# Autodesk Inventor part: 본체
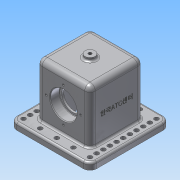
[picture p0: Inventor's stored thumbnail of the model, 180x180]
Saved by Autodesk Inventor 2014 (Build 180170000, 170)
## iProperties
Created: 2018-11
Part Number: 본체
Material: 알루미늄 6061
Document SubType Name: Modeling
Designer: Administrator
Density: 2.71 g/cm^3
Appearance: 알루미늄 - 평지
Mass: 1020.37 g
Surface Area: 790.556 cm^2
Volume: 376.52 cm^3
Author: Administrator
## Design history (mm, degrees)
sketch "스케치1"
  geometry: L1 (-60, -60)-(60, -60); L2 (60, -60)-(60, 60); L3 (60, 60)-(-60, 60); L4 (-60, 60)-(-60, -60); L5 (-60, -60)-(60, 60); L6 (60, -60)-(-60, 60); 1 further point
  constraints: 12 end point, 2 midpoint, 2 parallel, 1 horizontal, 1 perpendicular
  dimensions: "d0" = 120 distance of L3.end L2.end; "d1" = 120 distance of L2.end L1.end
extrude "돌출1" new body sketch "스케치1" distance "d2" = 10; taper "d3" = 0 deg
sketch "스케치2"
  geometry: L1 (-40, -40)-(40, -40); L2 (40, -40)-(40, 40); L3 (40, 40)-(-40, 40); L4 (-40, 40)-(-40, -40); L5 (-40, -40)-(40, 40); L6 (40, -40)-(-40, 40); 1 further point
  constraints: 12 end point, 2 midpoint, 2 parallel, 1 horizontal, 1 perpendicular
  dimensions: "d4" = 80 distance of L3.end L2.end; "d5" = 80 distance of L2.end L1.end
extrude "돌출2" join sketch "스케치2" distance "d6" = 80; taper "d7" = 0 deg
sketch "스케치4"
  geometry: C1 r 7.5 at (0, 0); 1 further point
  constraints: 1 centre point, 1 coincident
  dimensions: "d10" = 15 diameter of C1
extrude "돌출3" join sketch "스케치4" distance "d11" = 5; taper "d12" = 0 deg
node "작업 평면3"
sketch "스케치7"
  geometry: L1 (-60, 0)-(-60, 10) reference; L2 (-60, 10)-(-40, 10) reference; L3 (-40, 10)-(-40, 90) reference; L4 (-40, 90)-(-7.5, 90) reference; L5 (-7.5, 90)-(-7.5, 95) reference; L6 (-7.5, 95)-(7.5, 95) reference; L7 (7.5, 95)-(7.5, 90) reference; L8 (7.5, 90)-(40, 90) reference; L9 (40, 90)-(40, 10) reference; L10 (40, 10)-(60, 10) reference; L11 (60, 10)-(60, 0) reference; L12 (60, 0)-(-60, 0) reference; L13 (0, 0)-(0, 48); L14 (0, 48)-(-40, 48); L15 (-40, 48)-(-40, 68); L16 (-40, 68)-(-26, 68); L17 (-26, 68)-(-26, 64.5); L18 (-26, 64.5)-(-23, 64.5); L19 (-23, 64.5)-(-23, 48); L20 (23, 64.5)-(23, 48); L21 (26, 64.5)-(23, 64.5); L22 (26, 68)-(26, 64.5); L23 (40, 68)-(26, 68); L24 (40, 48)-(40, 68); L25 (0, 48)-(40, 48)
  constraints: 26 end point, 6 symmetric about line, 5 perpendicular, 4 point on line, 1 parallel
  dimensions: "d28" = 48 distance of L13.start L13.end; "d29" = 14 distance of L15.end L16.end; "d30" = 3 distance of L17.end L18.end; "d31" = 40 diameter of L16 L14; "d32" = 33 diameter of L18 L14
revolve "회전1" sketch "스케치7" stored, may be unused: angle "d33" = 90 deg
sketch "스케치8"
  geometry: L1 (30, -23)-(-30, -23); L2 (-30, -23)-(-30, 23); L3 (-30, 23)-(30, 23); L4 (30, 23)-(30, -23); L5 (30, -23)-(-30, 23); L6 (-30, -23)-(30, 23); 1 further point
  constraints: 12 end point, 2 midpoint, 2 parallel, 1 horizontal, 1 perpendicular
  dimensions: "d34" = 60 distance of L2.end L3.end; "d35" = 46 distance of L1.end L2.end
extrude "돌출4" cut sketch "스케치8" distance "d36" = 80; taper "d37" = 0 deg
sketch "스케치9" dims "d38" = 52
  geometry: L1 (100, 0)-(100, -10) reference; L2 (100, -10)-(-20, -10) reference; L3 (-20, -10)-(-20, 0) reference; L4 (-20, 0)-(0, 0) reference; L5 (0, 0)-(80, 0) reference; L6 (80, 0)-(100, 0) reference; L7 (0, 0)-(0, 80) reference; L8 (0, 80)-(80, 80) reference; L9 (80, 80)-(80, 0) reference; C1 r 20 at (40, 38) reference; C2 r 20 at (40, 38) reference; 3 further points
  constraints: 2 horizontal alignment, 1 coincident, 2 other
hole "구멍1" sketch "스케치9" at (66, 38) diameter "d39" = 3.242; stored, may be unused: countersink angle "d43" = 90 deg, drill point angle "d45" = 118 deg; dims "d40" = 8, "d41" = 4, "d42" = 2, "d44" = 10
hole "구멍2" diameter "d51" = 4.917; stored, may be unused: countersink angle "d55" = 90 deg, drill point angle "d57" = 0 deg; dims "d49" = 10, "d50" = 10, "d52" = 8, "d53" = 4, "d54" = 2, "d56" = 10
fillet "모깎기1" dims "d58" = 3
chamfer "모따기1" distance "d59" = 1; stored, may be unused: second distance "d60" = 2, angle "d61" = 45 deg
fillet "모깎기2" dims "d62" = 10
sketch "스케치10"
  geometry: A1 r 10 centre (-50, 50) between (-50, 60) and (-60, 50) reference; 2 further points
  constraints: 1 coincident
hole "구멍3" sketch "스케치10" at (-50, 50) diameter "d63" = 6.6; stored, may be unused: countersink angle "d67" = 90 deg, drill point angle "d69" = 0 deg; dims "d64" = 8, "d65" = 4, "d66" = 2, "d68" = 10
fillet "모깎기3" dims "d76" = 8
fillet "모깎기4" dims "d77" = 8
sketch "스케치13"
  geometry: L1 (10, -18)-(10, 82) reference; L2 (-85, 39.5)-(-85, 24.5) reference; 3 further points
  constraints: 1 horizontal alignment, 1 midpoint, 1 other
  dimensions: "d80" = 48 distance from line of L1 point (-38, 32)
feature "엠보싱1" sketch "스케치13" dims "d0" = 120, "d1" = 120, "d81" = 0.5, "d82" = 0
fillet "모깎기5" dims "d83" = 3
fillet "모깎기6" dims "d84" = 3
fillet "모깎기7" dims "d85" = 3
fillet "모깎기8" dims "d86" = 0.6
fillet "모깎기9" dims "d93" = 3
chamfer "모따기2" distance "d94" = 1; stored, may be unused: second distance "d95" = 2, angle "d96" = 45 deg
node "솔리드1"
pattern_circular "원형 패턴1" dims angle "d47" = 360 deg
mirror "대칭1"
mirror "대칭2"
mirror "대칭3"
pattern_linear "직사각형 패턴3" dims "d89" = 10
pattern_linear "직사각형 패턴4" dims "d92" = 25
mirror "대칭4"
mirror "대칭5"
node "절단 모서리 투영3"
node "절단 모서리 투영4"
other parameters: "d13" = 0
